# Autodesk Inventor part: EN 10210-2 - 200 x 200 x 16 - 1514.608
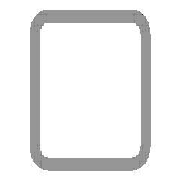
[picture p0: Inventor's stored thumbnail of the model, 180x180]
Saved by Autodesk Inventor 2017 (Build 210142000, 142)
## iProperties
_CCFamilyMember: 94
_CCFamilyDisplayName: DIN EN 10210-2 (Square) - Tube — Sizes in parentheses have been withdrawn
_FrameMemberDoc: Frame Member File
_Version: 15.0.0
_GetPNFromCC: 1
Created: 2017-11
Part Number: EN 10210-2 - 200 x 200 x 16 - 1514.608
Material: Steel, Mild
Description: Tube
Document SubType Name: Modeling
Standard: DIN
Designer: iusti
Standard Revision: 2006-07
Standards Organization: DIN
Language: en-US
Size Designation: 200 x 200 x 16
Categories: <MemberInstance><Categories><Category DisplayName="Structural Shapes" InternalName="089c4875-fa83-4c05-b084-43b9cc11f5ed" Mnemonic="GRDR"><CategoryParameter Dis
Stock Number: 200 x 200 x 16
Density: 7.85 g/cm^3
Appearance: Semi-Polished
Mass: 136747 g
Surface Area: 21484.9 cm^2
Volume: 17420 cm^3
IsCustomPart: 1
G_L: 1514.608 mm
G_W: 200.000 mm
G_H: 200.000 mm
+C71FC031-B3D7-48E0-8459-909C6924195B+CUTDETAIL1: Cut
Author: iusti
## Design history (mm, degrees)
node "Start plane"
node "End plane"
sketch "Sketch"
  geometry: L1 (-100, -76)-(-100, 76); L2 (-76, 100)-(76, 100); L3 (100, 76)-(100, -76); L4 (76, -100)-(-76, -100); L5 (-68, 84)-(68, 84); L6 (84, 68)-(84, -68); L7 (68, -84)-(-68, -84); L8 (-84, -68)-(-84, 68); L9 (0, 146.959)-(0, -146.959) reference; L10 (-146.959, 0)-(146.959, 0) reference; A1 r 24 centre (-76, -76) between (-100, -76) and (-76, -100); A2 r 24 centre (-76, 76) between (-76, 100) and (-100, 76); A3 r 24 centre (76, 76) between (100, 76) and (76, 100); A4 r 24 centre (76, -76) between (76, -100) and (100, -76); A5 r 16 centre (-68, -68) between (-84, -68) and (-68, -84); A6 r 16 centre (-68, 68) between (-68, 84) and (-84, 68); A7 r 16 centre (68, 68) between (84, 68) and (68, 84); A8 r 16 centre (68, -68) between (68, -84) and (84, -68)
  constraints: 16 end point, 16 point on circle, 16 tangent, 8 centre point, 6 equal radius, 4 parallel, 2 perpendicular, 2 other
  dimensions: "d7" = 24 radius of A1 (= G_IR); "d10" = 200 distance between parallel lines of L2 L4 (= G_H); "d11" = 200 distance between parallel lines of L1 L3 (= G_W); "d12" = 16 distance between parallel lines of L3 L6 (= G_T); "d15" = 100 distance between parallel lines of L2 L10 (= 0.5 x d10); "d16" = 100 distance between parallel lines of L9 L3 (= 0.5 x d11); "d19" = 16 radius of A5 (= G_T); "d20" = 16 distance between parallel lines of L4 L7 (= G_T)
extrude "Body" new body sketch "Sketch" stored distance "d3" = 1514.60835 (= G_L); taper "d4" = 0 deg
node "Driven Length"
  sketch "Sketch3"
    geometry: L1 (0, 0)-(10, 0) reference
    constraints: 2 end point, 1 horizontal
  workplane "Work Plane3"
  sketch "Sketch4"
    geometry: L1 (-2, 100)-(12, 100) reference; L2 (-2, 1614.608)-(12, 1614.608) reference
    dimensions: "d18" = 1514.60835 distance between parallel lines of L1 L2 (derived)
workplane "Work Plane4"
split "Split1"
body "Solid1"
other parameters: "G_W" = 200 [user parameter; used in 1 equation term], "G_H" = 200 [user parameter; used in 1 equation term], "G_T" = 16 [user parameter; used in 3 equation terms], "G_IR" = 24 [user parameter; used in 1 equation term], "G_L" = 1514.60835 (= d18) [user parameter; used in 1 equation term], "G_OFFSET_END" = 0 [user parameter; used in 1 equation term], "d14" = 1614.60835 (= G_OFFSET_END + B_L), "B_L" = 1614.60835 [user parameter; used in 1 equation term], "d17" = 90 deg
